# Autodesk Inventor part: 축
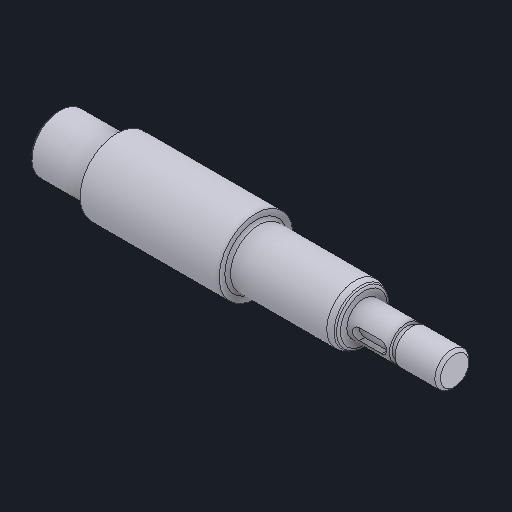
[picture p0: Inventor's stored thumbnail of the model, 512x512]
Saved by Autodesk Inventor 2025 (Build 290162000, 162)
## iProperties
Created: 2025-08
Part Number: 축
Material: 강철, 연강
Document SubType Name: Modeling
Designer: infra012
Density: 7.86 g/cm^3
Appearance: 기본값
Author: jhkim
Sending System: Autodesk Inventor 2026
Preprocessor: ST-DEVELOPER v20.1
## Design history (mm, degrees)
sketch "스케치1"
  geometry: 1 further point
  constraints: 1 other
feature "솔리드2"
node "솔리드1"
